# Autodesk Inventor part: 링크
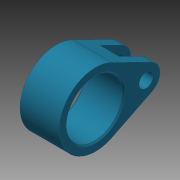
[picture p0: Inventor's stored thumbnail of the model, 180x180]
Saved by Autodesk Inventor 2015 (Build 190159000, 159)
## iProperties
Created: 2016-02
Part Number: 링크
Material: 강철, 연강
Document SubType Name: Modeling
Designer: test
Density: 1 g/cm^3
Appearance: 터키옥색
Author: test
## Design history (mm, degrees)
sketch "스케치1"
  geometry: L1 (20.222, 4.479)-(5.778, 11.645); L2 (20.222, -4.479)-(5.778, -11.645); A1 r 13 centre (0, 0) between (5.778, 11.645) and (5.778, -11.645); A2 r 5 centre (18, 0) between (20.222, -4.479) and (20.222, 4.479); 1 further point
  constraints: 4 end point, 4 point on circle, 4 tangent, 2 centre point, 1 coincident, 1 horizontal alignment
  dimensions: "d0" = 18 distance of point (0, 0) A2.centre; "d1" = 13 radius of A1; "d2" = 5 radius of A2
extrude "돌출1" new body sketch "스케치1" stored distance "d3" = 14; taper "d4" = 0 deg
sketch "스케치2"
  geometry: C1 r 10 at (0, 0); 1 further point
  constraints: 1 centre point, 1 coincident
  dimensions: "d5" = 20 diameter of C1
extrude "돌출2" cut sketch "스케치2" stored distance "d6" = 14; taper "d7" = 0 deg
sketch "스케치3"
  geometry: C1 r 2.5 at (18, 0); A1 r 5 centre (18, 0) between (20.222, -4.479) and (20.222, 4.479) reference; 1 further point
  constraints: 1 centre point, 1 coincident
  dimensions: "d8" = 5 diameter of C1
extrude "돌출3" cut sketch "스케치3" stored distance "d9" = 14; taper "d10" = 0 deg
sketch "스케치4"
  geometry: L1 (20.222, -4.479)-(5.778, -11.645) reference; L2 (5.778, 11.645)-(20.222, 4.479) reference; L3 (12, 8.558)-(12, -8.558); C1 r 2.5 at (18, 0) reference; C2 r 10 at (0, 0) reference; A1 r 13 centre (0, 0) between (5.778, 11.645) and (5.778, -11.645) reference; A2 r 5 centre (18, 0) between (20.222, -4.479) and (20.222, 4.479) reference; 1 further point
  constraints: 2 end point, 2 point on line, 1 vertical
  dimensions: "d11" = 12 distance from line of L3 point (0, 0)
extrude "돌출4" cut sketch "스케치4" stored distance "d12" = 7; taper "d13" = 0 deg
chamfer "모따기1" distance "d14" = 0.5; stored, may be unused: second distance "d15" = 2, angle "d16" = 45 deg
node "솔리드1"
node "절단 모서리 투영1"
